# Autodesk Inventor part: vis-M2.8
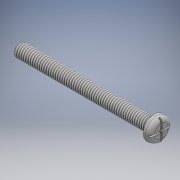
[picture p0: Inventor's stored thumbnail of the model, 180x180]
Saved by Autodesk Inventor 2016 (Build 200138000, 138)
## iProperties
Created: 2018-03
Part Number: vis-M2.8
Material: Générique
Document SubType Name: Modeling
Designer: Bruno
Density: 1 g/cm^3
Appearance: Par défaut
Author: Bruno
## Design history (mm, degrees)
sketch "Esquisse1"
  geometry: C1 r 1.4 at (0, 0); 1 further point
  constraints: 1 centre point, 1 coincident
  dimensions: "d0" = 2.8 diameter of C1
extrude "Extrusion1" new body sketch "Esquisse1" distance "d1" = 30; taper "d2" = 0 deg
sketch "Esquisse2"
  geometry: C1 r 2.5 at (0, 0); 1 further point
  constraints: 1 centre point, 1 coincident
  dimensions: "d3" = 5 diameter of C1
extrude "Extrusion2" join sketch "Esquisse2" distance "d4" = 1.5; taper "d5" = 0 deg
fillet "Congé1" dims "d6" = 1
sketch "Esquisse3"
  geometry: L1 (-0.204, 3.169)-(0.204, 3.169); L2 (0.204, 3.169)-(0.204, -3.51); L3 (0.204, -3.51)-(-0.204, -3.51); L4 (-0.204, -3.51)-(-0.204, 3.169); L5 (-2.999, 0.183)-(3.203, 0.183); L6 (3.203, 0.183)-(3.203, -0.161); L7 (3.203, -0.161)-(-2.999, -0.161); L8 (-2.999, -0.161)-(-2.999, 0.183); 1 further point
  constraints: 16 end point, 4 parallel, 2 horizontal, 2 perpendicular
extrude "Extrusion3" cut sketch "Esquisse3" distance "d7" = 0.5; taper "d8" = 0 deg
chamfer "Chanfrein1" distance "d9" = 0.5; stored, may be unused: second distance "d10" = 2, angle "d11" = 45 deg
feature "Filetage1" dims "d12" = 10, "d13" = 0
node "Solide1"
